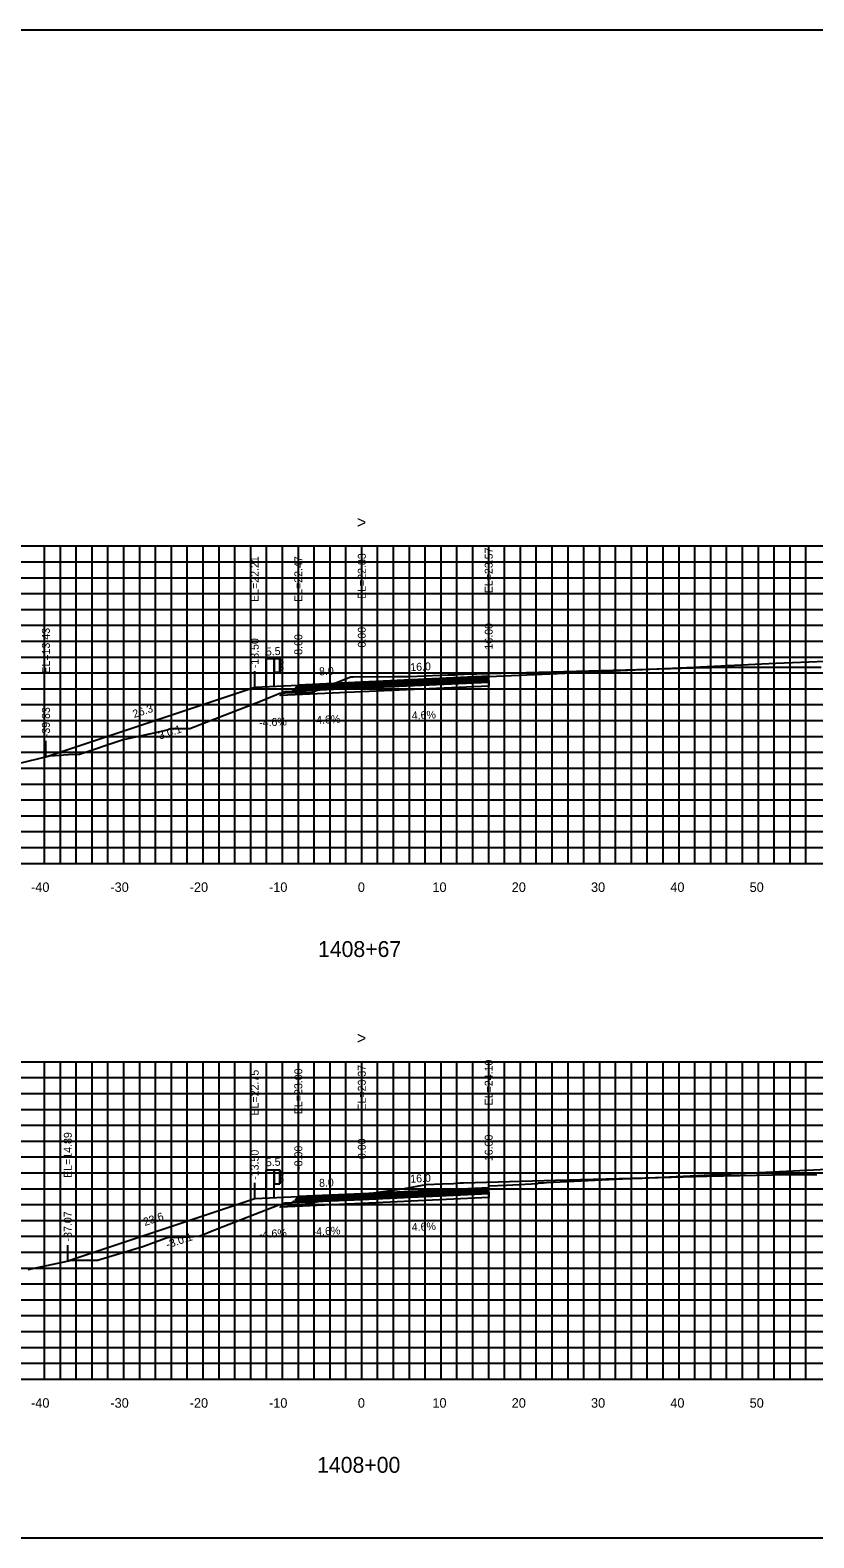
# Model space of a CAD drawing. Extents: x 1797652 to 1804159, y 242516 to 246906.
# Drawn here: x 1803962.7 to 1804061.5, y 242516 to 242706 of the extents above; entities that cross this region are included whole.
import ezdxf

# ---------------------------------------------------------------- set-up
doc = ezdxf.new("R2010")
doc.units = 0
for name, color, linetype in [('1', 7, 'Continuous'), ('10', 7, 'Continuous'), ('2', 7, 'Continuous'), ('3', 7, 'Continuous'), ('4', 7, 'Continuous'), ('60', 7, 'Continuous'), ('BASE', 7, 'Continuous'), ('CL-CNST', 7, 'Continuous'), ('DRAINAGE', 7, 'Continuous'), ('Level 62', 7, 'Continuous'), ('LOWER BINDER', 7, 'Continuous'), ('M-ROADS', 7, 'Continuous'), ('UPPER BINDER', 7, 'Continuous')]:
    doc.layers.add(name, color=color, linetype=linetype)

msp = doc.modelspace()

# ---------------------------------------------------------------- linework, layer by layer
for p, q in [((1804020.49, 242624.57), (1804020.49, 242626.57)), ((1803990.99, 242623.21), (1803990.99, 242625.21)), ((1803996.49, 242623.47), (1803996.49, 242625.47)), ((1804004.49, 242623.83), (1804004.49, 242625.83)), ((1803964.66, 242614.44), (1803964.66, 242616.44)), ((1804020.49, 242560.1), (1804020.49, 242562.1)), ((1803990.99, 242558.75), (1803990.99, 242560.75)), ((1803996.49, 242559), (1803996.49, 242561)), ((1804004.49, 242559.37), (1804004.49, 242561.37)), ((1803967.42, 242550.89), (1803967.42, 242552.89))]:
    msp.add_line(p, q)
msp.add_lwpolyline([(1803854.49, 242516), (1804154.49, 242516), (1804154.49, 242706), (1803854.49, 242706)], close=True)
at = {"layer": '2'}
for points in [[(1804020.49, 242624.57), (1804004.49, 242623.83), (1803996.49, 242623.47), (1803996.33, 242623.31), (1804004.49, 242623.68), (1804020.49, 242624.42)], [(1804020.49, 242560.1), (1804004.49, 242559.37), (1803996.49, 242559), (1803996.33, 242558.84), (1804004.49, 242559.22), (1804020.49, 242559.95)]]:
    msp.add_lwpolyline(points, close=True, dxfattribs=at)
at = {"layer": '60'}
for p, q in [((1803854.49, 242601), (1804154.49, 242601)), ((1803964.49, 242600.94), (1803964.49, 242601)), ((1803974.49, 242600.94), (1803974.49, 242601)), ((1803984.49, 242600.94), (1803984.49, 242601)), ((1803994.49, 242600.94), (1803994.49, 242601)), ((1804004.49, 242600.94), (1804004.49, 242601)), ((1804014.49, 242600.94), (1804014.49, 242601)), ((1804024.49, 242600.94), (1804024.49, 242601)), ((1804034.49, 242600.94), (1804034.49, 242601)), ((1804044.49, 242600.94), (1804044.49, 242601)), ((1804054.49, 242600.94), (1804054.49, 242601)), ((1803854.49, 242536), (1804154.49, 242536)), ((1803964.49, 242535.94), (1803964.49, 242536)), ((1803974.49, 242535.94), (1803974.49, 242536)), ((1803984.49, 242535.94), (1803984.49, 242536)), ((1803994.49, 242535.94), (1803994.49, 242536)), ((1804004.49, 242535.94), (1804004.49, 242536)), ((1804014.49, 242535.94), (1804014.49, 242536)), ((1804024.49, 242535.94), (1804024.49, 242536)), ((1804034.49, 242535.94), (1804034.49, 242536)), ((1804044.49, 242535.94), (1804044.49, 242536)), ((1804054.49, 242535.94), (1804054.49, 242536))]:
    msp.add_line(p, q, dxfattribs=at)
at = {"layer": 'BASE'}
for points in [[(1803994.73, 242622.67), (1803995.73, 242622.71), (1804004.49, 242623.11), (1804020.49, 242623.85), (1804020.49, 242623.35), (1804004.49, 242622.61), (1803994.21, 242622.14)], [(1803994.73, 242558.2), (1803995.73, 242558.25), (1804004.49, 242558.65), (1804020.49, 242559.38), (1804020.49, 242558.88), (1804004.49, 242558.15), (1803994.21, 242557.68)]]:
    msp.add_lwpolyline(points, close=True, dxfattribs=at)
at = {"layer": 'CL-CNST'}
for points in [[(1804020.49, 242624.55), (1804031.06, 242625.03), (1804032.55, 242625.1), (1804041.69, 242625.51), (1804044.62, 242625.65), (1804052.32, 242626), (1804056.68, 242626.21), (1804062.96, 242626.5)], [(1803964.66, 242614.44), (1803990.99, 242623.21), (1803996.49, 242623.47), (1804004.49, 242623.83), (1804020.49, 242624.57)], [(1804020.49, 242560.36), (1804022.74, 242560.46), (1804026.69, 242560.65), (1804026.72, 242560.68), (1804026.77, 242560.73), (1804027.41, 242560.76), (1804027.77, 242560.77), (1804037.36, 242561.23), (1804039.85, 242561.34), (1804041.52, 242561.42), (1804050.28, 242561.84), (1804051.92, 242561.92), (1804052.05, 242561.92), (1804063.99, 242562.49)], [(1803967.42, 242550.89), (1803990.99, 242558.75), (1803996.49, 242559), (1804004.49, 242559.37), (1804020.49, 242560.1)]]:
    msp.add_lwpolyline(points, dxfattribs=at)
at = {"layer": 'DRAINAGE'}
for p, q in [((1803992.4, 242626.83), (1803992.4, 242623.27)), ((1803992.4, 242626.83), (1803994.15, 242626.83)), ((1803993.4, 242626.83), (1803993.4, 242623.31)), ((1803993.45, 242626.83), (1803993.45, 242625.08)), ((1803994.1, 242626.83), (1803994.1, 242625.08)), ((1803994.15, 242626.83), (1803994.15, 242625.08)), ((1803994.15, 242626.68), (1803994.52, 242626.39)), ((1803994.52, 242626.31), (1803994.15, 242626.03)), ((1803993.4, 242625.08), (1803994.15, 242625.08)), ((1803994.15, 242625.89), (1803994.52, 242625.59)), ((1803994.52, 242625.52), (1803994.15, 242625.23)), ((1803992.4, 242562.37), (1803992.4, 242558.8)), ((1803992.4, 242562.37), (1803994.15, 242562.37)), ((1803993.4, 242562.37), (1803993.4, 242558.84)), ((1803993.45, 242562.37), (1803993.45, 242560.62)), ((1803994.1, 242562.37), (1803994.1, 242560.62)), ((1803994.15, 242562.37), (1803994.15, 242560.62)), ((1803994.15, 242562.22), (1803994.52, 242561.92)), ((1803994.52, 242561.85), (1803994.15, 242561.56)), ((1803993.4, 242560.62), (1803994.15, 242560.62)), ((1803994.15, 242561.42), (1803994.52, 242561.13)), ((1803994.52, 242561.05), (1803994.15, 242560.77))]:
    msp.add_line(p, q, dxfattribs=at)
for centre in [(1803994.48, 242626.35), (1803994.48, 242625.56), (1803994.48, 242561.89), (1803994.48, 242561.09)]:
    msp.add_arc(centre, 0.05, 313.3792, 45, dxfattribs=at)
at = {"layer": 'Level 62'}
for p, q in [((1803854.49, 242641), (1804154.49, 242641)), ((1803964.49, 242601), (1803964.49, 242641)), ((1803966.49, 242601), (1803966.49, 242641)), ((1803968.49, 242601), (1803968.49, 242641)), ((1803970.49, 242601), (1803970.49, 242641)), ((1803972.49, 242601), (1803972.49, 242641)), ((1803974.49, 242601), (1803974.49, 242641)), ((1803976.49, 242601), (1803976.49, 242641)), ((1803978.49, 242601), (1803978.49, 242641)), ((1803980.49, 242601), (1803980.49, 242641)), ((1803982.49, 242601), (1803982.49, 242641)), ((1803984.49, 242601), (1803984.49, 242641)), ((1803986.49, 242601), (1803986.49, 242641)), ((1803988.49, 242601), (1803988.49, 242641)), ((1803990.49, 242601), (1803990.49, 242641)), ((1803992.49, 242601), (1803992.49, 242641)), ((1803994.49, 242601), (1803994.49, 242641)), ((1803996.49, 242601), (1803996.49, 242641)), ((1803998.49, 242601), (1803998.49, 242641)), ((1804000.49, 242601), (1804000.49, 242641)), ((1804002.49, 242601), (1804002.49, 242641)), ((1804004.49, 242601), (1804004.49, 242641)), ((1804006.49, 242601), (1804006.49, 242641)), ((1804008.49, 242601), (1804008.49, 242641)), ((1804010.49, 242601), (1804010.49, 242641)), ((1804012.49, 242601), (1804012.49, 242641)), ((1804014.49, 242601), (1804014.49, 242641)), ((1804016.49, 242601), (1804016.49, 242641)), ((1804018.49, 242601), (1804018.49, 242641)), ((1804020.49, 242601), (1804020.49, 242641)), ((1804022.49, 242601), (1804022.49, 242641)), ((1804024.49, 242601), (1804024.49, 242641)), ((1804026.49, 242601), (1804026.49, 242641)), ((1804028.49, 242601), (1804028.49, 242641)), ((1804030.49, 242601), (1804030.49, 242641)), ((1804032.49, 242601), (1804032.49, 242641)), ((1804034.49, 242601), (1804034.49, 242641)), ((1804036.49, 242601), (1804036.49, 242641)), ((1804038.49, 242601), (1804038.49, 242641)), ((1804040.49, 242601), (1804040.49, 242641)), ((1804042.49, 242601), (1804042.49, 242641)), ((1804044.49, 242601), (1804044.49, 242641)), ((1804046.49, 242601), (1804046.49, 242641)), ((1804048.49, 242601), (1804048.49, 242641)), ((1804050.49, 242601), (1804050.49, 242641)), ((1804052.49, 242601), (1804052.49, 242641)), ((1804054.49, 242601), (1804054.49, 242641)), ((1804056.49, 242601), (1804056.49, 242641)), ((1804058.49, 242601), (1804058.49, 242641)), ((1804060.49, 242601), (1804060.49, 242641)), ((1803854.49, 242639), (1804154.49, 242639)), ((1803854.49, 242637), (1804154.49, 242637)), ((1803854.49, 242635), (1804154.49, 242635)), ((1803854.49, 242633), (1804154.49, 242633)), ((1803854.49, 242631), (1804154.49, 242631)), ((1803854.49, 242629), (1804154.49, 242629)), ((1803854.49, 242627), (1804154.49, 242627)), ((1803854.49, 242625), (1804154.49, 242625)), ((1803854.49, 242623), (1804154.49, 242623)), ((1803854.49, 242621), (1804154.49, 242621)), ((1803854.49, 242619), (1804154.49, 242619)), ((1803854.49, 242617), (1804154.49, 242617)), ((1803854.49, 242615), (1804154.49, 242615)), ((1803854.49, 242613), (1804154.49, 242613)), ((1803854.49, 242611), (1804154.49, 242611)), ((1803854.49, 242609), (1804154.49, 242609)), ((1803854.49, 242607), (1804154.49, 242607)), ((1803854.49, 242605), (1804154.49, 242605)), ((1803854.49, 242603), (1804154.49, 242603)), ((1803854.49, 242601), (1804154.49, 242601)), ((1803854.49, 242576), (1804154.49, 242576)), ((1803964.49, 242536), (1803964.49, 242576)), ((1803966.49, 242536), (1803966.49, 242576)), ((1803968.49, 242536), (1803968.49, 242576)), ((1803970.49, 242536), (1803970.49, 242576)), ((1803972.49, 242536), (1803972.49, 242576)), ((1803974.49, 242536), (1803974.49, 242576)), ((1803976.49, 242536), (1803976.49, 242576)), ((1803978.49, 242536), (1803978.49, 242576)), ((1803980.49, 242536), (1803980.49, 242576)), ((1803982.49, 242536), (1803982.49, 242576)), ((1803984.49, 242536), (1803984.49, 242576)), ((1803986.49, 242536), (1803986.49, 242576)), ((1803988.49, 242536), (1803988.49, 242576)), ((1803990.49, 242536), (1803990.49, 242576)), ((1803992.49, 242536), (1803992.49, 242576)), ((1803994.49, 242536), (1803994.49, 242576)), ((1803996.49, 242536), (1803996.49, 242576)), ((1803998.49, 242536), (1803998.49, 242576)), ((1804000.49, 242536), (1804000.49, 242576)), ((1804002.49, 242536), (1804002.49, 242576)), ((1804004.49, 242536), (1804004.49, 242576)), ((1804006.49, 242536), (1804006.49, 242576)), ((1804008.49, 242536), (1804008.49, 242576)), ((1804010.49, 242536), (1804010.49, 242576)), ((1804012.49, 242536), (1804012.49, 242576)), ((1804014.49, 242536), (1804014.49, 242576)), ((1804016.49, 242536), (1804016.49, 242576)), ((1804018.49, 242536), (1804018.49, 242576)), ((1804020.49, 242536), (1804020.49, 242576)), ((1804022.49, 242536), (1804022.49, 242576)), ((1804024.49, 242536), (1804024.49, 242576)), ((1804026.49, 242536), (1804026.49, 242576)), ((1804028.49, 242536), (1804028.49, 242576)), ((1804030.49, 242536), (1804030.49, 242576)), ((1804032.49, 242536), (1804032.49, 242576)), ((1804034.49, 242536), (1804034.49, 242576)), ((1804036.49, 242536), (1804036.49, 242576)), ((1804038.49, 242536), (1804038.49, 242576)), ((1804040.49, 242536), (1804040.49, 242576)), ((1804042.49, 242536), (1804042.49, 242576)), ((1804044.49, 242536), (1804044.49, 242576)), ((1804046.49, 242536), (1804046.49, 242576)), ((1804048.49, 242536), (1804048.49, 242576)), ((1804050.49, 242536), (1804050.49, 242576)), ((1804052.49, 242536), (1804052.49, 242576)), ((1804054.49, 242536), (1804054.49, 242576)), ((1804056.49, 242536), (1804056.49, 242576)), ((1804058.49, 242536), (1804058.49, 242576)), ((1804060.49, 242536), (1804060.49, 242576)), ((1803854.49, 242574), (1804154.49, 242574)), ((1803854.49, 242572), (1804154.49, 242572)), ((1803854.49, 242570), (1804154.49, 242570)), ((1803854.49, 242568), (1804154.49, 242568)), ((1803854.49, 242566), (1804154.49, 242566)), ((1803854.49, 242564), (1804154.49, 242564)), ((1803854.49, 242562), (1804154.49, 242562)), ((1803854.49, 242560), (1804154.49, 242560)), ((1803854.49, 242558), (1804154.49, 242558)), ((1803854.49, 242556), (1804154.49, 242556)), ((1803854.49, 242554), (1804154.49, 242554)), ((1803854.49, 242552), (1804154.49, 242552)), ((1803854.49, 242550), (1804154.49, 242550)), ((1803854.49, 242548), (1804154.49, 242548)), ((1803854.49, 242546), (1804154.49, 242546)), ((1803854.49, 242544), (1804154.49, 242544)), ((1803854.49, 242542), (1804154.49, 242542)), ((1803854.49, 242540), (1804154.49, 242540)), ((1803854.49, 242538), (1804154.49, 242538)), ((1803854.49, 242536), (1804154.49, 242536))]:
    msp.add_line(p, q, dxfattribs=at)
at = {"layer": 'LOWER BINDER'}
for points in [[(1804004.49, 242623.3), (1804020.49, 242624.04), (1804020.49, 242623.85), (1804004.49, 242623.11), (1803995.73, 242622.71), (1803995.93, 242622.91)], [(1804004.49, 242558.84), (1804020.49, 242559.57), (1804020.49, 242559.38), (1804004.49, 242558.65), (1803995.73, 242558.25), (1803995.93, 242558.44)]]:
    msp.add_lwpolyline(points, close=True, dxfattribs=at)
at = {"layer": 'M-ROADS'}
for points in [[(1803960.98, 242613.53), (1803965.14, 242614.55), (1803967.53, 242614.7), (1803968.9, 242614.78), (1803974.29, 242616.55), (1803979.46, 242617.72), (1803979.95, 242617.84), (1803980.27, 242617.97), (1803980.39, 242617.98), (1803982.79, 242618), (1803991.72, 242621.44), (1803994.16, 242622.45), (1803995.45, 242622.53), (1803997.08, 242622.53), (1803998.11, 242622.53), (1804000.03, 242623.29), (1804003.11, 242624.5), (1804003.22, 242624.5), (1804003.4, 242624.5), (1804008.39, 242624.53), (1804010.37, 242624.56), (1804011.48, 242624.59), (1804015.34, 242624.74), (1804016.16, 242624.77), (1804016.37, 242624.78), (1804017.41, 242624.84), (1804033.1, 242625.27), (1804037.76, 242625.4), (1804046.24, 242625.62), (1804050.68, 242625.71), (1804059.93, 242625.73), (1804062.42, 242625.73)], [(1803962.44, 242549.83), (1803967.94, 242551), (1803968.41, 242551), (1803969.19, 242551), (1803971.18, 242551), (1803976.88, 242552.73), (1803980.09, 242553.89), (1803980.81, 242553.89), (1803982.01, 242553.89), (1803983.99, 242554.03), (1803986.26, 242554.95), (1803994.02, 242557.98), (1803996.81, 242558.06), (1803997.12, 242558.07), (1803999.94, 242558.56), (1804001.29, 242558.77), (1804005.06, 242559.35), (1804009.87, 242560.04), (1804012.62, 242560.51), (1804014.65, 242560.61), (1804016.07, 242560.67), (1804016.85, 242560.72), (1804017.32, 242560.75), (1804030.4, 242561.11), (1804043.49, 242561.46), (1804048.02, 242561.56), (1804056.28, 242561.74), (1804061.85, 242561.79)]]:
    msp.add_lwpolyline(points, dxfattribs=at)
at = {"layer": 'UPPER BINDER'}
for points in [[(1804020.49, 242624.42), (1804004.49, 242623.68), (1803996.33, 242623.31), (1803996.13, 242623.11), (1804004.49, 242623.49), (1804020.49, 242624.23)], [(1804020.49, 242559.95), (1804004.49, 242559.22), (1803996.33, 242558.84), (1803996.13, 242558.64), (1804004.49, 242559.03), (1804020.49, 242559.76)]]:
    msp.add_lwpolyline(points, close=True, dxfattribs=at)

# ---------------------------------------------------------------- texts
for p in [(1803978.61, 242616.45), (1803979.99, 242552.45)]:
    msp.add_text('-3.0:1', height=1, rotation=18.4348).set_placement(p)
at = {"layer": '1'}
for s, p in [('1408+67', (1803998.97, 242589.2)), ('1408+00', (1803998.86, 242524.2))]:
    msp.add_text(s, height=2, dxfattribs=at).set_placement(p)
at = {"layer": '10'}
for s, p in [('-40', (1803962.79, 242597.4)), ('-30', (1803972.79, 242597.4)), ('-20', (1803982.79, 242597.4)), ('-10', (1803992.79, 242597.4)), ('0', (1804003.99, 242597.4)), ('10', (1804013.39, 242597.4)), ('20', (1804023.39, 242597.4)), ('30', (1804033.39, 242597.4)), ('40', (1804043.39, 242597.4)), ('50', (1804053.39, 242597.4)), ('-40', (1803962.79, 242532.4)), ('-30', (1803972.79, 242532.4)), ('-20', (1803982.79, 242532.4)), ('-10', (1803992.79, 242532.4)), ('0', (1804003.99, 242532.4)), ('10', (1804013.39, 242532.4)), ('20', (1804023.39, 242532.4)), ('30', (1804033.39, 242532.4)), ('40', (1804043.39, 242532.4)), ('50', (1804053.39, 242532.4))]:
    msp.add_text(s, height=1.2, dxfattribs=at).set_placement(p)
at = {"layer": '3'}
for s, p in [('EL=22.21', (1803991.49, 242633.94)), ('EL=22.47', (1803996.99, 242633.94)), ('EL=22.83', (1804004.99, 242634.31)), ('EL=23.57', (1804020.99, 242635.04)), ('EL=13.43', (1803965.16, 242624.91)), ('0.00', (1804004.99, 242628.2)), ('16.00', (1804020.99, 242627.94)), ('-13.50', (1803991.49, 242625.59)), ('-8.00', (1803996.99, 242626.84)), ('-39.83', (1803965.16, 242616.89)), ('EL=22.75', (1803991.49, 242569.22)), ('EL=23.00', (1803996.99, 242569.39)), ('EL=23.37', (1804004.99, 242569.84)), ('EL=24.10', (1804020.99, 242570.5)), ('EL=14.89', (1803967.92, 242561.36)), ('0.00', (1804004.99, 242563.73)), ('16.00', (1804020.99, 242563.47)), ('-13.50', (1803991.49, 242561.12)), ('-8.00', (1803996.99, 242562.37)), ('-37.07', (1803967.92, 242553.35))]:
    msp.add_text(s, height=1, rotation=90, dxfattribs=at).set_placement(p)
at = {"layer": '4'}
for s, rotation, p in [('5.5', 2.6337, (1803992.41, 242627.18)), ('16.0', 2.6337, (1804010.62, 242625.22)), ('8.0', 2.6337, (1803999.12, 242624.69)), ('26.3', 18.4348, (1803975.79, 242619.3)), ('-4.6%', 2.6337, (1803991.56, 242618.23)), ('-4.6%', 2.6337, (1803998.31, 242618.54)), ('4.6%', 2.6337, (1804010.81, 242619.12)), ('5.5', 2.6337, (1803992.41, 242562.82)), ('16.0', 2.6337, (1804010.62, 242560.75)), ('8.0', 2.6337, (1803999.12, 242560.22)), ('23.6', 18.4348, (1803977.14, 242555.29)), ('-4.6%', 2.6337, (1803991.56, 242553.77)), ('-4.6%', 2.6337, (1803998.31, 242554.08)), ('4.6%', 2.6337, (1804010.81, 242554.65))]:
    msp.add_text(s, height=1, rotation=rotation, dxfattribs=at).set_placement(p)
at = {"layer": '60'}
for p in [(1804003.88, 242643.25), (1804003.88, 242578.25)]:
    msp.add_text('>', height=1.5, dxfattribs=at).set_placement(p)

doc.saveas('drawing.dxf')
